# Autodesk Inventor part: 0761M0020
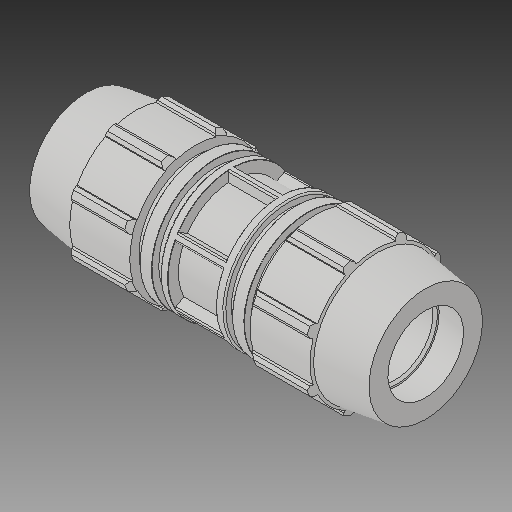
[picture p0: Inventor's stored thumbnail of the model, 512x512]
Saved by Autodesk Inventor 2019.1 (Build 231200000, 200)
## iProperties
Created: 2017-02
Part Number: 0761M0020
Material: Generic
Description: PLASSON REPAIR COUPLER 2'' - 2''
Document SubType Name: Modeling
Designer: KIM
Mass: 2544.89 g
Surface Area: 2949.22 cm^2
Volume: 2544.89 cm^3
Density: 1 g/cm^3
Appearance: Default
Author: KIM
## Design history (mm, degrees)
derived "0761M.ipt"
feature "Solid1::0761M.ipt"
tag "TaggingFeature1"
body "Solid1"
other parameters: "d1" = 269.748, "d2" = 60.1, "d4" = 22.479, "d5" = 38.53543, "d7" = 113.03, "d8" = 84.7725, "d9" = 38.53543, "d11" = 9.35567, "d12" = 90.424, "d13" = 120 deg, "d14" = 90.15, "d15" = 8 deg, "d16" = 101.727, "d19" = 35 deg, "d20" = 17.5 deg, "d21" = 105.1179, "d23" = 0, "d25" = 360 deg, "d27" = 2.2606, "d33" = 0.2, "d34" = 5.6515, "d36" = 0, "d37" = 1.202, "d38" = 1.202, "d40" = 360 deg, "d42" = 48.55464, "d43" = 3.3909, "d46" = 1.803, "d50" = 6.36899, "d51" = 90.424, "d52" = 6.36899, "d_" = 60.1, "E_" = 113.03, "H_" = 269.748, "l_" = 112.014, "d49" = 22.09365
